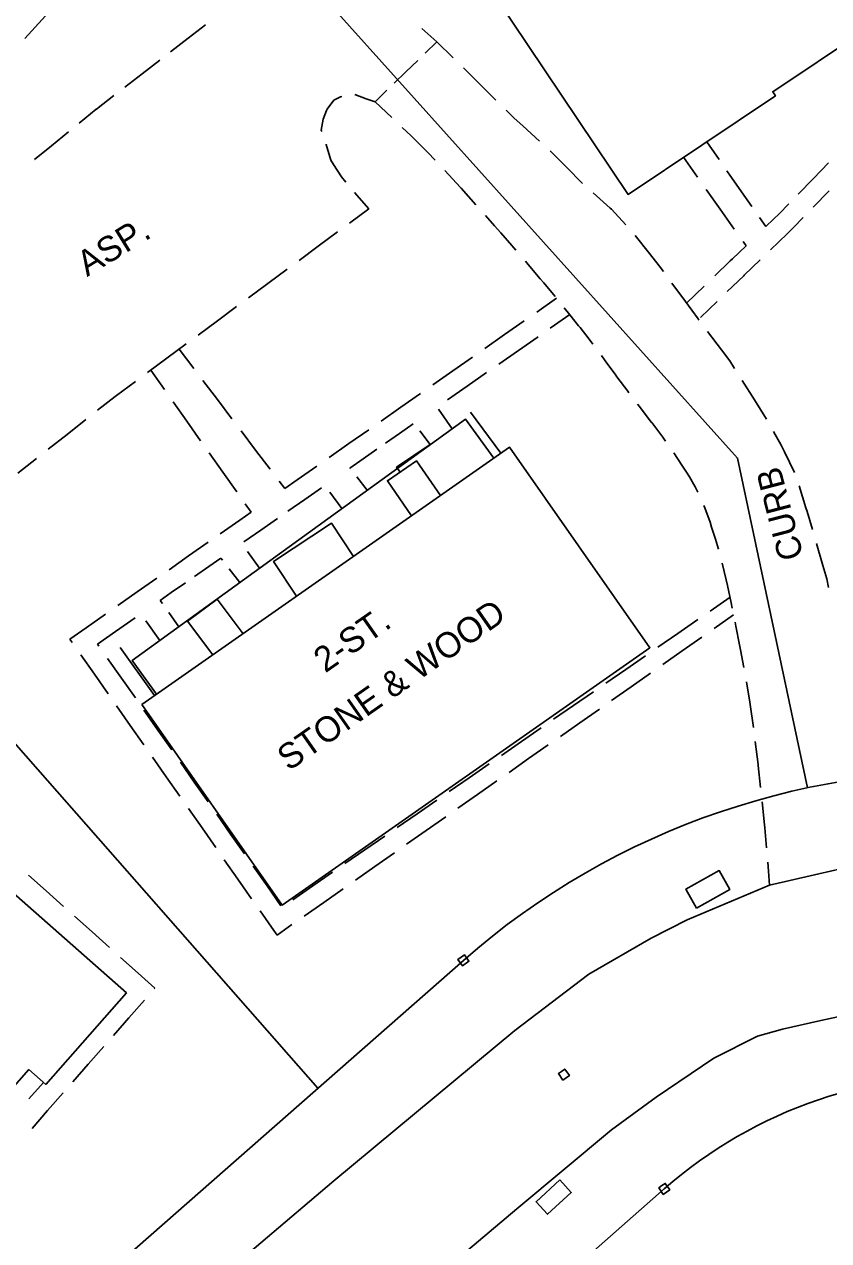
# Model space of a CAD drawing. Extents: x 2443269 to 2494951, y 591171 to 622130.
# Drawn here: x 2462776.3 to 2462908.5, y 604393.7 to 604593.6 of the extents above; entities that cross this region are included whole.
import ezdxf

# ---------------------------------------------------------------- set-up
doc = ezdxf.new("R2010")
doc.units = 0
for name, color, linetype in [('SURVEY - NON-TRANSPORTATION - Buildings', 7, 'Continuous'), ('SURVEY - NON-TRANSPORTATION - Buildings Text', 7, 'Continuous'), ('SURVEY - NON-TRANSPORTATION - Features', 7, 'Continuous'), ('SURVEY - PROPERTY - Property Lines', 7, 'Continuous'), ('SURVEY - PROPERTY - ROW Lines', 7, 'Continuous'), ('SURVEY - TRANSPORTATION - Features', 7, 'Continuous'), ('SURVEY - TRANSPORTATION - Features Text', 7, 'Continuous'), ('SURVEY - TRANSPORTATION - Roads', 7, 'Continuous'), ('SURVEY - UTILITIES - Sanitary Sewer with Text', 7, 'Continuous')]:
    doc.layers.add(name, color=color, linetype=linetype)

msp = doc.modelspace()

# ---------------------------------------------------------------- linework, layer by layer
at = {"layer": 'SURVEY - NON-TRANSPORTATION - Buildings'}
for points in [[(2462848.145, 604606.514), (2462872.072, 604622.541), (2462871.238, 604623.785), (2462901.603, 604644.126), (2462902.741, 604642.423), (2462925.864, 604657.912), (2462953.292, 604616.967), (2462929.568, 604601.075), (2462928.768, 604602.269), (2462899.28, 604582.515), (2462899.709, 604581.872), (2462875.51, 604565.661)], [(2462795.589, 604481.803), (2462856.032, 604524.09), (2462879.099, 604491.121), (2462818.657, 604448.834)], [(2462717.686, 604409.376), (2462728.447, 604421.574), (2462725.51, 604424.162), (2462749.47, 604451.321), (2462752.246, 604448.874), (2462762.922, 604460.977), (2462793.066, 604434.382), (2462779.805, 604419.349), (2462777.049, 604421.78), (2462758.26, 604400.481), (2462760.911, 604398.142), (2462747.564, 604383.014)]]:
    msp.add_lwpolyline(points, close=True, dxfattribs=at)
at = {"layer": 'SURVEY - NON-TRANSPORTATION - Features'}
for p, q in [((2462854.614, 604523.099), (2462849.605, 604529.874)), ((2462797.676, 604483.263), (2462792.056, 604491.17))]:
    msp.add_line(p, q, dxfattribs=at)
for points in [[(2462798.036, 604483.516), (2462794.031, 604489.041), (2462848.768, 604528.719), (2462853.437, 604522.276)], [(2462842.974, 604524.562), (2462837.459, 604520.789), (2462838.043, 604519.992)], [(2462839.92, 604512.817), (2462835.969, 604518.568), (2462840.74, 604521.846), (2462844.664, 604516.137)], [(2462830.376, 604506.141), (2462826.786, 604511.587), (2462817.242, 604505.297), (2462821.006, 604499.585)], [(2462812.226, 604493.444), (2462807.961, 604499.12), (2462803.125, 604495.484), (2462807.265, 604489.973)]]:
    msp.add_lwpolyline(points, dxfattribs=at)
for points in [[(2462886.753, 604448.342), (2462885.011, 604451.462), (2462890.471, 604454.507), (2462892.213, 604451.387)], [(2462864.263, 604403.647), (2462866.156, 604401.607), (2462862.285, 604398.011), (2462860.392, 604400.052)]]:
    msp.add_lwpolyline(points, close=True, dxfattribs=at)
at = {"layer": 'SURVEY - PROPERTY - Property Lines'}
msp.add_line((2462824.514, 604418.72), (2462713.619, 604544.957), dxfattribs=at)
msp.add_lwpolyline([(2462904.989, 604468.111), (2462893.507, 604522.298), (2462803.137, 604622.935)], dxfattribs=at)
for points in [[(2462848.075, 604440.278), (2462848.606, 604440.653), (2462849.356, 604439.591), (2462848.295, 604438.841), (2462847.544, 604439.902)], [(2462864.574, 604421.495), (2462865.105, 604421.871), (2462865.856, 604420.809), (2462864.794, 604420.059), (2462864.044, 604421.12)], [(2462881.074, 604402.713), (2462881.605, 604403.089), (2462882.355, 604402.027), (2462881.294, 604401.277), (2462880.543, 604402.338)]]:
    msp.add_lwpolyline(points, close=True, dxfattribs=at)
at = {"layer": 'SURVEY - PROPERTY - ROW Lines'}
for p, q in [((2462271.547, 603932.954), (2462848.45, 604439.747)), ((2462762.663, 604297.832), (2462881.449, 604402.183))]:
    msp.add_line(p, q, dxfattribs=at)
for radius in [124.999, 75]:
    msp.add_arc((2462930.948, 604345.836), radius, 41.29809, 131.29837, dxfattribs=at)
at = {"layer": 'SURVEY - TRANSPORTATION - Features'}
for p, q in [((2462806.053, 604593.534), (2462803.193, 604591.307)), ((2462844.08, 604590.73), (2462841.591, 604592.943)), ((2462803.193, 604591.307), (2462800.333, 604589.079)), ((2462842.147, 604588.857), (2462844.08, 604590.73)), ((2462844.08, 604590.73), (2462844.08, 604590.73)), ((2462844.08, 604590.73), (2462846.758, 604588.09)), ((2462798.543, 604587.691), (2462795.672, 604585.478)), ((2462839.008, 604585.812), (2462840.94, 604587.686)), ((2462795.672, 604585.478), (2462792.801, 604583.264)), ((2462837.075, 604583.939), (2462839.008, 604585.812)), ((2462848.432, 604586.44), (2462851.11, 604583.799)), ((2462833.935, 604580.894), (2462835.868, 604582.768)), ((2462851.11, 604583.799), (2462853.789, 604581.159)), ((2462791.006, 604581.881), (2462788.135, 604579.668)), ((2462826.045, 604579.68), (2462827.157, 604581.127)), ((2462827.157, 604581.127), (2462828.256, 604581.662)), ((2462828.256, 604581.662), (2462828.487, 604581.74)), ((2462830.584, 604582.085), (2462832.449, 604581.344)), ((2462832.449, 604581.344), (2462833.935, 604580.894)), ((2462836.686, 604578.281), (2462833.935, 604580.894)), ((2462833.935, 604580.894), (2462833.935, 604580.894)), ((2462833.935, 604580.894), (2462833.935, 604580.894)), ((2462788.092, 604579.635), (2462785.323, 604577.38)), ((2462788.135, 604579.668), (2462788.092, 604579.635)), ((2462825.389, 604578.043), (2462825.945, 604579.431)), ((2462825.945, 604579.431), (2462826.045, 604579.68)), ((2462855.463, 604579.509), (2462856.806, 604578.184)), ((2462825.097, 604576.222), (2462825.389, 604578.043)), ((2462839.841, 604575.284), (2462838.406, 604576.648)), ((2462856.806, 604578.184), (2462858.191, 604576.921)), ((2462858.191, 604576.921), (2462860.969, 604574.386)), ((2462783.566, 604575.95), (2462780.754, 604573.661)), ((2462825.166, 604576.014), (2462825.097, 604576.222)), ((2462841.126, 604574.002), (2462839.841, 604575.284)), ((2462780.754, 604573.661), (2462777.943, 604571.373)), ((2462825.891, 604573.844), (2462825.871, 604573.904)), ((2462826.685, 604571.282), (2462825.891, 604573.844)), ((2462842.62, 604572.512), (2462841.126, 604574.002)), ((2462862.705, 604572.801), (2462865.356, 604570.133)), ((2462888.43, 604574.316), (2462890.469, 604571.382)), ((2462827.112, 604570.589), (2462826.685, 604571.282)), ((2462843.781, 604571.293), (2462842.62, 604572.512)), ((2462886.922, 604568.509), (2462884.624, 604571.767)), ((2462884.624, 604571.767), (2462884.624, 604571.767)), ((2462905.952, 604568.268), (2462908.439, 604570.832)), ((2462828.387, 604568.526), (2462827.112, 604570.589)), ((2462847.977, 604566.775), (2462845.416, 604569.575)), ((2462865.356, 604570.133), (2462868.007, 604567.465)), ((2462891.743, 604569.549), (2462893.781, 604566.615)), ((2462829.126, 604567.666), (2462828.387, 604568.526)), ((2462848.053, 604566.692), (2462847.977, 604566.775)), ((2462850.504, 604563.945), (2462848.053, 604566.692)), ((2462903.464, 604565.704), (2462905.952, 604568.268)), ((2462832.892, 604563.276), (2462830.574, 604565.977)), ((2462869.747, 604565.887), (2462872.58, 604563.414)), ((2462890.656, 604563.215), (2462888.358, 604566.473)), ((2462893.781, 604566.615), (2462895.82, 604563.681)), ((2462905.934, 604563.536), (2462908.559, 604566.242)), ((2462829.733, 604560.938), (2462832.892, 604563.276)), ((2462832.892, 604563.276), (2462832.892, 604563.276)), ((2462872.58, 604563.414), (2462872.79, 604563.23)), ((2462872.79, 604563.23), (2462875.152, 604560.671)), ((2462892.954, 604559.958), (2462890.656, 604563.215)), ((2462900.323, 604562.466), (2462901.909, 604564.101)), ((2462853.574, 604560.471), (2462852.076, 604562.169)), ((2462897.094, 604561.847), (2462898.135, 604560.35)), ((2462898.135, 604560.35), (2462899.392, 604561.566)), ((2462899.392, 604561.566), (2462900.323, 604562.466)), ((2462902.643, 604560.143), (2462904.293, 604561.844)), ((2462824.599, 604557.138), (2462827.758, 604559.476)), ((2462854.581, 604559.319), (2462853.574, 604560.471)), ((2462856.38, 604557.263), (2462854.581, 604559.319)), ((2462876.674, 604558.882), (2462879.019, 604555.942)), ((2462898.925, 604556.549), (2462901.636, 604559.17)), ((2462901.636, 604559.17), (2462902.643, 604560.143)), ((2462821.439, 604554.8), (2462824.599, 604557.138)), ((2462857.072, 604556.457), (2462856.38, 604557.263)), ((2462892.647, 604555.044), (2462894.89, 604557.213)), ((2462894.89, 604557.213), (2462894.39, 604557.922)), ((2462859.096, 604554.106), (2462858.619, 604554.66)), ((2462879.019, 604555.942), (2462880.625, 604553.929)), ((2462889.781, 604552.274), (2462892.298, 604554.707)), ((2462892.298, 604554.707), (2462892.647, 604555.044)), ((2462894.578, 604552.348), (2462897.23, 604554.911)), ((2462816.305, 604551), (2462819.465, 604553.338)), ((2462861.071, 604551.764), (2462859.096, 604554.106)), ((2462880.625, 604553.929), (2462881.325, 604552.971)), ((2462813.146, 604548.661), (2462816.305, 604551)), ((2462861.639, 604551.091), (2462861.071, 604551.764)), ((2462863.495, 604548.845), (2462861.639, 604551.091)), ((2462882.711, 604551.073), (2462884.929, 604548.036)), ((2462891.808, 604549.67), (2462894.519, 604552.291)), ((2462894.519, 604552.291), (2462894.578, 604552.348)), ((2462885.123, 604547.771), (2462887.989, 604550.542)), ((2462808.012, 604544.861), (2462811.171, 604547.2)), ((2462860.482, 604546.309), (2462863.729, 604548.585)), ((2462863.729, 604548.585), (2462863.729, 604548.585)), ((2462865.94, 604545.848), (2462864.996, 604547.009)), ((2462884.929, 604548.036), (2462887.006, 604545.192)), ((2462887.403, 604545.412), (2462890.114, 604548.033)), ((2462804.852, 604542.523), (2462808.012, 604544.861)), ((2462855.206, 604542.611), (2462858.453, 604544.886)), ((2462862.718, 604543.651), (2462865.937, 604545.898)), ((2462865.937, 604545.898), (2462865.937, 604545.898)), ((2462867.374, 604544.052), (2462865.94, 604545.848)), ((2462887.006, 604545.192), (2462887.151, 604545.001)), ((2462867.616, 604543.749), (2462867.374, 604544.052)), ((2462869.089, 604541.856), (2462867.616, 604543.749)), ((2462888.569, 604543.126), (2462890.838, 604540.127)), ((2462799.718, 604538.723), (2462802.878, 604541.061)), ((2462851.96, 604540.335), (2462855.206, 604542.611)), ((2462857.487, 604540), (2462860.706, 604542.247)), ((2462869.695, 604541.051), (2462869.089, 604541.856)), ((2462796.559, 604536.385), (2462799.718, 604538.723)), ((2462801.734, 604540.215), (2462804.128, 604537.055)), ((2462846.684, 604536.636), (2462849.93, 604538.912)), ((2462854.269, 604537.753), (2462857.487, 604540)), ((2462872.026, 604537.902), (2462871.111, 604539.149)), ((2462890.838, 604540.127), (2462892.223, 604538.296)), ((2462799.34, 604533.572), (2462797.082, 604536.774)), ((2462797.082, 604536.774), (2462797.082, 604536.774)), ((2462843.437, 604534.361), (2462846.684, 604536.636)), ((2462873.353, 604536.088), (2462872.026, 604537.902)), ((2462892.223, 604538.296), (2462893.002, 604537.055)), ((2462791.425, 604532.585), (2462794.584, 604534.923)), ((2462805.624, 604535.079), (2462808.018, 604531.919)), ((2462849.038, 604534.103), (2462852.257, 604536.349)), ((2462873.663, 604535.665), (2462873.353, 604536.088)), ((2462875.444, 604533.28), (2462873.663, 604535.665)), ((2462894.251, 604535.064), (2462896.25, 604531.878)), ((2462838.161, 604530.662), (2462841.408, 604532.938)), ((2462845.819, 604531.856), (2462849.038, 604534.103)), ((2462875.623, 604533.047), (2462875.444, 604533.28)), ((2462788.332, 604530.159), (2462791.216, 604532.43)), ((2462791.216, 604532.43), (2462791.425, 604532.585)), ((2462803.01, 604528.37), (2462800.752, 604531.572)), ((2462808.018, 604531.919), (2462810.411, 604528.758)), ((2462834.915, 604528.387), (2462838.161, 604530.662)), ((2462877.36, 604530.776), (2462877.064, 604531.164)), ((2462879.319, 604528.237), (2462877.36, 604530.776)), ((2462896.25, 604531.878), (2462898.249, 604528.693)), ((2462783.314, 604526.207), (2462786.402, 604528.639)), ((2462846.57, 604527.125), (2462844.34, 604530.355)), ((2462805.268, 604525.169), (2462803.01, 604528.37)), ((2462811.908, 604526.782), (2462814.301, 604523.622)), ((2462829.639, 604524.688), (2462832.886, 604526.964)), ((2462837.933, 604526.352), (2462840.204, 604527.938)), ((2462841.288, 604526.761), (2462842.974, 604524.562)), ((2462879.379, 604528.157), (2462879.319, 604528.237)), ((2462881.199, 604525.734), (2462879.379, 604528.157)), ((2462899.422, 604526.657), (2462900.648, 604524.428)), ((2462780.226, 604523.776), (2462783.314, 604526.207)), ((2462826.392, 604522.412), (2462829.639, 604524.688)), ((2462835.661, 604524.766), (2462837.933, 604526.352)), ((2462881.642, 604525.112), (2462881.199, 604525.734)), ((2462808.938, 604519.967), (2462806.68, 604523.168)), ((2462814.301, 604523.622), (2462816.695, 604520.461)), ((2462831.969, 604522.189), (2462834.241, 604523.775)), ((2462842.974, 604524.562), (2462842.974, 604524.562)), ((2462884.358, 604521.167), (2462883.012, 604523.176)), ((2462900.648, 604524.428), (2462901.18, 604523.333)), ((2462901.18, 604523.333), (2462902.824, 604519.95)), ((2462775.208, 604519.824), (2462778.296, 604522.256)), ((2462821.117, 604518.714), (2462824.363, 604520.99)), ((2462829.795, 604520.671), (2462831.969, 604522.189)), ((2462829.868, 604520.578), (2462829.795, 604520.671)), ((2462885.09, 604520.002), (2462884.358, 604521.167)), ((2462811.196, 604516.765), (2462808.938, 604519.967)), ((2462819.093, 604517.295), (2462821.117, 604518.714)), ((2462832.639, 604517.03), (2462830.934, 604519.213)), ((2462885.569, 604519.241), (2462885.09, 604520.002)), ((2462886.524, 604517.581), (2462885.569, 604519.241)), ((2462818.191, 604518.486), (2462819.093, 604517.295)), ((2462822.359, 604515.481), (2462825.111, 604517.403)), ((2462826.508, 604516.73), (2462828.456, 604513.998)), ((2462886.961, 604516.704), (2462886.524, 604517.581)), ((2462903.617, 604517.744), (2462904.716, 604514.147)), ((2462813.558, 604513.417), (2462812.608, 604514.764)), ((2462819.608, 604513.56), (2462822.359, 604515.481)), ((2462811.7, 604512.115), (2462813.558, 604513.417)), ((2462828.456, 604513.998), (2462828.456, 604513.998)), ((2462888.971, 604511.774), (2462888.112, 604514.103)), ((2462904.716, 604514.147), (2462904.906, 604513.526)), ((2462904.906, 604513.526), (2462905.783, 604510.541)), ((2462808.492, 604509.866), (2462811.7, 604512.115)), ((2462815.136, 604510.438), (2462817.888, 604512.359)), ((2462889.23, 604510.977), (2462888.971, 604511.774)), ((2462889.877, 604508.978), (2462889.23, 604510.977)), ((2462812.384, 604508.517), (2462815.136, 604510.438)), ((2462890.336, 604507.348), (2462889.877, 604508.978)), ((2462803.279, 604506.212), (2462806.487, 604508.46)), ((2462814.962, 604504.215), (2462812.987, 604506.928)), ((2462906.446, 604508.286), (2462907.506, 604504.677)), ((2462800.071, 604503.963), (2462803.279, 604506.212)), ((2462806.606, 604504.485), (2462808.597, 604505.875)), ((2462808.597, 604505.875), (2462808.861, 604505.531)), ((2462891.622, 604502.269), (2462890.951, 604505.058)), ((2462907.506, 604504.677), (2462908.161, 604502.45)), ((2462804.26, 604502.847), (2462806.606, 604504.485)), ((2462809.947, 604504.11), (2462811.685, 604501.836)), ((2462794.858, 604500.309), (2462798.066, 604502.557)), ((2462800.447, 604500.185), (2462802.793, 604501.823)), ((2462811.685, 604501.836), (2462811.685, 604501.836)), ((2462891.817, 604501.364), (2462891.622, 604502.269)), ((2462892.426, 604498.532), (2462891.817, 604501.364)), ((2462908.161, 604502.45), (2462908.453, 604501.04)), ((2462791.649, 604498.06), (2462794.858, 604500.309)), ((2462798.63, 604498.916), (2462800.447, 604500.185)), ((2462799, 604498.387), (2462798.63, 604498.916)), ((2462892.252, 604499.425), (2462888.987, 604497.165)), ((2462786.436, 604494.405), (2462789.644, 604496.654)), ((2462801.665, 604494.576), (2462800.025, 604496.921)), ((2462892.605, 604497.652), (2462892.426, 604498.532)), ((2462791.277, 604493.784), (2462794.533, 604496.056)), ((2462796.24, 604495.547), (2462798.561, 604492.325)), ((2462886.946, 604495.752), (2462883.68, 604493.493)), ((2462892.836, 604496.521), (2462889.629, 604494.271)), ((2462893.823, 604491.608), (2462893.207, 604494.69)), ((2462783.768, 604492.535), (2462786.436, 604494.405)), ((2462788.335, 604491.731), (2462791.277, 604493.784)), ((2462883.68, 604493.493), (2462880.415, 604491.233)), ((2462887.624, 604492.865), (2462884.417, 604490.615)), ((2462784.146, 604491.995), (2462783.768, 604492.535)), ((2462788.555, 604491.417), (2462788.335, 604491.731)), ((2462893.984, 604490.803), (2462893.823, 604491.608)), ((2462894.533, 604487.881), (2462893.984, 604490.803)), ((2462787.798, 604486.78), (2462785.551, 604489.989)), ((2462792.256, 604486.13), (2462789.979, 604489.383)), ((2462878.374, 604489.82), (2462875.109, 604487.561)), ((2462884.417, 604490.615), (2462881.21, 604488.366)), ((2462790.045, 604483.57), (2462787.798, 604486.78)), ((2462875.109, 604487.561), (2462871.843, 604485.301)), ((2462879.205, 604486.959), (2462875.998, 604484.71)), ((2462794.534, 604482.877), (2462792.256, 604486.13)), ((2462875.998, 604484.71), (2462872.79, 604482.46)), ((2462895.5, 604482.197), (2462894.945, 604485.546)), ((2462869.803, 604483.888), (2462866.537, 604481.629)), ((2462793.696, 604478.355), (2462791.449, 604481.565)), ((2462798.235, 604477.591), (2462795.957, 604480.844)), ((2462866.537, 604481.629), (2462863.272, 604479.369)), ((2462870.786, 604481.054), (2462867.578, 604478.804)), ((2462896.093, 604478.045), (2462895.557, 604481.801)), ((2462867.578, 604478.804), (2462864.371, 604476.554)), ((2462795.943, 604475.146), (2462793.696, 604478.355)), ((2462800.513, 604474.338), (2462798.235, 604477.591)), ((2462861.231, 604477.956), (2462857.965, 604475.697)), ((2462857.965, 604475.697), (2462854.7, 604473.437)), ((2462862.366, 604475.148), (2462859.159, 604472.898)), ((2462896.87, 604471.928), (2462896.402, 604475.694)), ((2462799.594, 604469.931), (2462797.347, 604473.14)), ((2462859.159, 604472.898), (2462855.952, 604470.648)), ((2462804.214, 604469.052), (2462801.936, 604472.305)), ((2462852.659, 604472.024), (2462849.394, 604469.765)), ((2462897.286, 604468.157), (2462896.888, 604471.78)), ((2462801.841, 604466.722), (2462799.594, 604469.931)), ((2462806.491, 604465.799), (2462804.214, 604469.052)), ((2462849.394, 604469.765), (2462846.128, 604467.505)), ((2462853.947, 604469.242), (2462850.74, 604466.992)), ((2462850.74, 604466.992), (2462847.532, 604464.742)), ((2462805.493, 604461.506), (2462803.246, 604464.716)), ((2462844.087, 604466.092), (2462840.822, 604463.832)), ((2462897.908, 604462.022), (2462897.538, 604465.799)), ((2462810.192, 604460.513), (2462807.915, 604463.766)), ((2462840.822, 604463.832), (2462837.557, 604461.573)), ((2462845.528, 604463.336), (2462842.321, 604461.086)), ((2462807.74, 604458.297), (2462805.493, 604461.506)), ((2462842.321, 604461.086), (2462839.113, 604458.836)), ((2462897.954, 604461.547), (2462897.908, 604462.022)), ((2462898.247, 604458.243), (2462897.954, 604461.547)), ((2462812.47, 604457.26), (2462810.192, 604460.513)), ((2462835.516, 604460.16), (2462832.25, 604457.9)), ((2462832.25, 604457.9), (2462828.985, 604455.641)), ((2462837.109, 604457.43), (2462833.901, 604455.18)), ((2462811.391, 604453.082), (2462809.144, 604456.291)), ((2462816.171, 604451.973), (2462813.893, 604455.226)), ((2462833.901, 604455.18), (2462830.694, 604452.931)), ((2462898.571, 604454.399), (2462898.448, 604455.88)), ((2462779.862, 604451.184), (2462776.983, 604453.765)), ((2462813.638, 604449.873), (2462811.391, 604453.082)), ((2462826.944, 604454.228), (2462823.679, 604451.968)), ((2462898.758, 604452.099), (2462898.571, 604454.399)), ((2462782.741, 604448.604), (2462779.862, 604451.184)), ((2462818.448, 604448.72), (2462816.171, 604451.973)), ((2462823.679, 604451.968), (2462820.413, 604449.709)), ((2462828.689, 604451.524), (2462825.482, 604449.275)), ((2462825.482, 604449.275), (2462822.275, 604447.025)), ((2462787.419, 604444.41), (2462784.54, 604446.991)), ((2462817.289, 604444.657), (2462815.042, 604447.867)), ((2462820.27, 604445.619), (2462817.82, 604443.9)), ((2462790.298, 604441.83), (2462787.419, 604444.41)), ((2462817.82, 604443.9), (2462817.289, 604444.657)), ((2462794.976, 604437.636), (2462792.097, 604440.217)), ((2462797.725, 604435.173), (2462794.976, 604437.636)), ((2462797.609, 604435.041), (2462797.725, 604435.173)), ((2462793.472, 604430.313), (2462796.018, 604433.223)), ((2462790.925, 604427.404), (2462793.472, 604430.313)), ((2462786.787, 604422.677), (2462789.334, 604425.586)), ((2462784.241, 604419.767), (2462786.787, 604422.677)), ((2462779.418, 604419.691), (2462777.035, 604416.983)), ((2462780.103, 604415.04), (2462782.65, 604417.949)), ((2462777.557, 604412.13), (2462780.103, 604415.04))]:
    msp.add_line(p, q, dxfattribs=at)
at = {"layer": 'SURVEY - TRANSPORTATION - Roads'}
for p, q in [((2462888.112, 604514.103), (2462887.928, 604514.54)), ((2462893.207, 604494.69), (2462893.077, 604495.329)), ((2462895.557, 604481.801), (2462895.5, 604482.197)), ((2462896.888, 604471.78), (2462896.87, 604471.928))]:
    msp.add_line(p, q, dxfattribs=at)
for points in [[(2462761.731, 604347.187), (2462795.176, 604376.298), (2462827.141, 604403.51), (2462856.885, 604428.188), (2462869.034, 604437.456), (2462879.319, 604443.365), (2462885.192, 604446.403), (2462898.758, 604452.099), (2462916.868, 604456.282), (2462921.782, 604456.288)], [(2462914.04, 604431.311), (2462907.183, 604429.835), (2462900.871, 604428.444), (2462896.753, 604427.302), (2462889.598, 604423.641), (2462880.129, 604417.263), (2462872.771, 604411.869), (2462857.206, 604398.9), (2462841.826, 604385.928)]]:
    msp.add_lwpolyline(points, dxfattribs=at)
at = {"layer": 'SURVEY - UTILITIES - Sanitary Sewer with Text'}
msp.add_line((2462776.402, 604591.303), (2462783.128, 604598.704), dxfattribs=at)

# ---------------------------------------------------------------- texts
at = {"layer": 'SURVEY - NON-TRANSPORTATION - Buildings Text'}
for s, height, p in [('STONE & WOOD', 4.16599, (2462819.749, 604470.766)), ('2-ST.', 4.166, (2462825.738, 604486.892))]:
    msp.add_text(s, height=height, rotation=34.97722, dxfattribs=at).set_placement(p)
at = {"layer": 'SURVEY - TRANSPORTATION - Features Text'}
for s, height, rotation, p in [('ASP.', 4.166, 31.64222, (2462786.607, 604552.052)), ('CURB', 4.101, 104.6, (2462904.368, 604506.111))]:
    msp.add_text(s, height=height, rotation=rotation, dxfattribs=at).set_placement(p)

doc.saveas('drawing.dxf')
